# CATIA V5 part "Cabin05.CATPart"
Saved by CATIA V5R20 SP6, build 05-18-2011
Part number: Cabin05
Bounding box of the stored display mesh (mm): x 578.019 to 721.019, y 0 to 20, z 1145 to 1385
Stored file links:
  E:\#01 CATIA Lecture Materials\#06 DMU\#01 DMU KIN Page01 EX01\#01 CATPart\Cabin05.CATPart
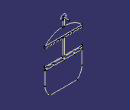
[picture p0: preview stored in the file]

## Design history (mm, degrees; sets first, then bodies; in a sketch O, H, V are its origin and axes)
Set1
  DatumCurve1 "Curve.1 ( *CRV37 - wsp *MASTER -  )"
  DatumCurve2 "Curve.2 ( *CRV38 - wsp *MASTER -  )"
  DatumCurve3 "Curve.3 ( *CRV39 - wsp *MASTER -  )"
  DatumCurve4 "Curve.4 ( *CRV40 - wsp *MASTER -  )"
  DatumCurve5 "Curve.5 ( *CRV41 - wsp *MASTER -  )"
  DatumCurve6 "Curve.6 ( *CRV42 - wsp *MASTER -  )"
  DatumCurve7 "Curve.7 ( *CRV43 - wsp *MASTER -  )"
  DatumCurve8 "Curve.8 ( *CRV44 - wsp *MASTER -  )"
  DatumCurve9 "Curve.9 ( *CRV45 - wsp *MASTER -  )"
  DatumCurve10 "Curve.10 ( *CRV46 - wsp *MASTER -  )"
  DatumCurve11 "Curve.11 ( *CRV47 - wsp *MASTER -  )"
  DatumCurve12 "Curve.12 ( *CRV48 - wsp *MASTER -  )"
  DatumCurve13 "Curve.13 ( *CRV49 - wsp *MASTER -  )"
  DatumCurve14 "Curve.14 ( *CRV50 - wsp *MASTER -  )"
  DatumCurve15 "Curve.15 ( *CRV51 - wsp *MASTER -  )"
  DatumCurve16 "Curve.16 ( *CRV52 - wsp *MASTER -  )"
  DatumCurve17 "Curve.17 ( *CRV53 - wsp *MASTER -  )"
  Line1 "Line.1 ( *LN83 - wsp *MASTER -  )": stored without definition
  Line2 "Line.2 ( *LN84 - wsp *MASTER -  )": stored without definition
  Line3 "Line.3 ( *LN85 - wsp *MASTER -  )": stored without definition
  Line4 "Line.4 ( *LN86 - wsp *MASTER -  )": stored without definition
  Line5 "Line.5 ( *LN87 - wsp *MASTER -  )": stored without definition
  Line6 "Line.6 ( *LN88 - wsp *MASTER -  )": stored without definition
  Line7 "Line.7 ( *LN89 - wsp *MASTER -  )": stored without definition
  Line8 "Line.8 ( *LN90 - wsp *MASTER -  )": stored without definition
  Line9 "Line.9 ( *LN91 - wsp *MASTER -  )": stored without definition
  Line10 "Line.10 ( *LN92 - wsp *MASTER -  )": stored without definition
  Line11 "Line.11 ( *LN93 - wsp *MASTER -  )": stored without definition
  Line12 "Line.12 ( *LN94 - wsp *MASTER -  )": stored without definition
  Line13 "Line.13 ( *LN95 - wsp *MASTER -  )": stored without definition
  Line14 "Line.14 ( *LN96 - wsp *MASTER -  )": stored without definition
  Line15 "Line.15 ( *LN97 - wsp *MASTER -  )": stored without definition
  Line16 "Line.16 ( *LN98 - wsp *MASTER -  )": stored without definition
  Line17 "Line.17 ( *LN99 - wsp *MASTER -  )": stored without definition
  Line18 "Line.18 ( *LN100 - wsp *MASTER -  )": stored without definition
  Line19 "Line.19 ( *LN101 - wsp *MASTER -  )": stored without definition
  Line20 "Line.20 ( *LN102 - wsp *MASTER -  )": stored without definition
  Line21 "Line.21 ( *LN103 - wsp *MASTER -  )": stored without definition
  Line22 "Line.22 ( *LN104 - wsp *MASTER -  )": stored without definition
  Line23 "Line.23 ( *LN105 - wsp *MASTER -  )": stored without definition
  Line24 "Line.24 ( *LN106 - wsp *MASTER -  )": stored without definition
  Line25 "Line.25 ( *LN107 - wsp *MASTER -  )": stored without definition
  Line26 "Line.26 ( *LN108 - wsp *MASTER -  )": stored without definition
  Line27 "Line.27 ( *LN109 - wsp *MASTER -  )": stored without definition
  Line28 "Line.28 ( *LN110 - wsp *MASTER -  )": stored without definition
  Line29 "Line.29 ( *LN111 - wsp *MASTER -  )": stored without definition
  Line30 "Line.30 ( *LN112 - wsp *MASTER -  )": stored without definition
  Line31: stored without definition
Body1 (main body)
